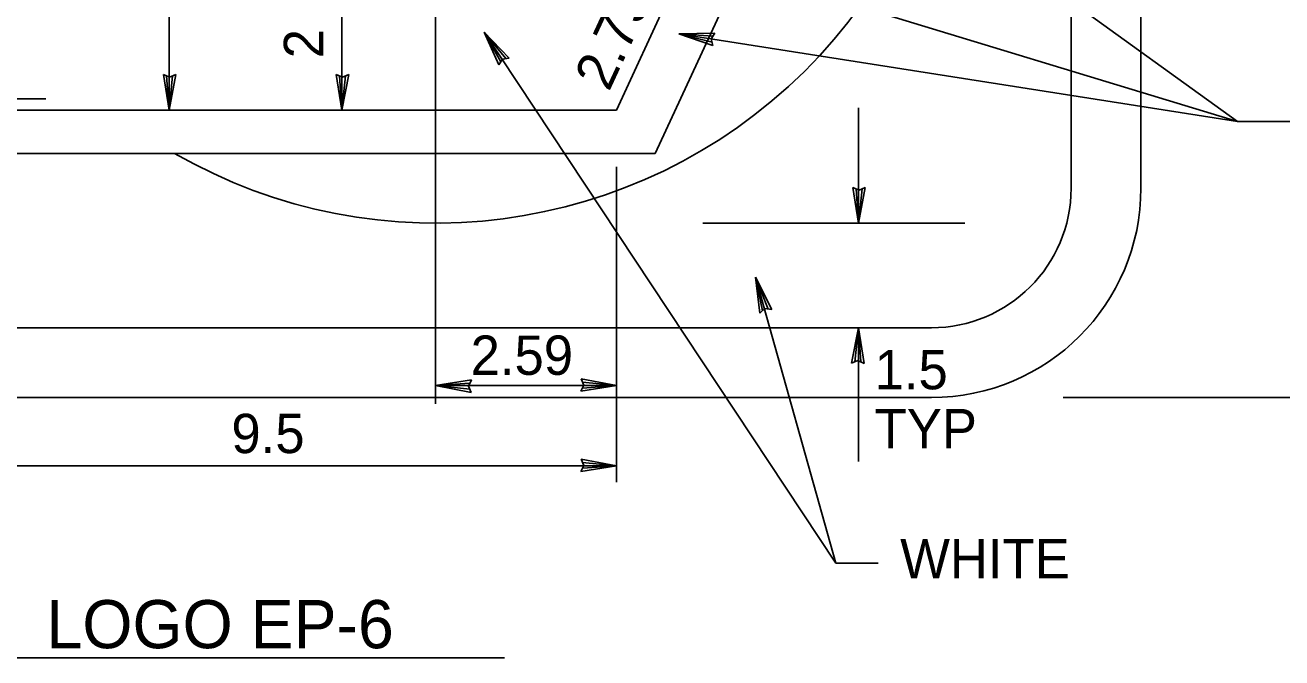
# Model space of a CAD drawing. Extents: x 10268197 to 10269179, y 2141503 to 2142677.
# Drawn here: x 10268537.59 to 10268560.08, y 2141960.82 to 2141972.15 of the extents above; entities that cross this region are included whole.
import ezdxf

# ---------------------------------------------------------------- set-up
doc = ezdxf.new("R2010")
doc.units = 0
for name, color, linetype in [('1', 7, 'Continuous'), ('21', 7, 'Continuous'), ('Default', 7, 'Continuous'), ('TextMisc', 7, 'Continuous'), ('TextShtNo', 7, 'Continuous')]:
    doc.layers.add(name, color=color, linetype=linetype)

msp = doc.modelspace()

# ---------------------------------------------------------------- linework, layer by layer
at = {"layer": '1'}
for p, q in [((10268549.369, 2141977.587), (10268559.29, 2141970.427)), ((10268545.142, 2141974.73), (10268559.29, 2141970.427)), ((10268549.292, 2141971.995), (10268559.29, 2141970.427)), ((10268559.29, 2141970.427), (10268560.422, 2141970.427))]:
    msp.add_line(p, q, dxfattribs=at)
at = {"layer": '21'}
msp.add_line((10268536.456, 2141960.817), (10268546.168, 2141960.817), dxfattribs=at)
at = {"layer": 'Default'}
for p, q in [((10268556.312, 2141969.23), (10268556.312, 2141986.73)), ((10268540.165, 2141970.63), (10268540.165, 2141985.364)), ((10268544.937, 2141965.367), (10268544.937, 2141977.98)), ((10268549.691, 2141973.913), (10268548.175, 2141970.63)), ((10268543.258, 2141970.63), (10268543.258, 2141973.085)), ((10268550.385, 2141973.136), (10268548.869, 2141969.854)), ((10268545.806, 2141972.028), (10268552.098, 2141962.512)), ((10268545.806, 2141972.028), (10268546.255, 2141971.562)), ((10268545.806, 2141972.028), (10268546.07, 2141971.437)), ((10268545.806, 2141972.028), (10268546.105, 2141971.491)), ((10268545.806, 2141972.028), (10268546.193, 2141971.551)), ((10268549.292, 2141971.995), (10268549.937, 2141972.007)), ((10268549.292, 2141971.995), (10268549.901, 2141971.785)), ((10268549.292, 2141971.995), (10268549.886, 2141971.848)), ((10268549.292, 2141971.995), (10268549.902, 2141971.953)), ((10268549.871, 2141971.904), (10268549.937, 2141972.007)), ((10268549.901, 2141971.785), (10268549.871, 2141971.904)), ((10268546.07, 2141971.437), (10268546.136, 2141971.54)), ((10268546.136, 2141971.54), (10268546.255, 2141971.562)), ((10268540.165, 2141970.63), (10268540.064, 2141971.269)), ((10268540.175, 2141971.219), (10268540.064, 2141971.269)), ((10268540.165, 2141970.63), (10268540.122, 2141971.242)), ((10268540.165, 2141970.63), (10268540.288, 2141971.266)), ((10268540.165, 2141970.63), (10268540.229, 2141971.241)), ((10268540.288, 2141971.266), (10268540.175, 2141971.219)), ((10268543.258, 2141970.63), (10268543.157, 2141971.269)), ((10268543.268, 2141971.219), (10268543.157, 2141971.269)), ((10268543.258, 2141970.63), (10268543.215, 2141971.242)), ((10268543.258, 2141970.63), (10268543.381, 2141971.266)), ((10268543.258, 2141970.63), (10268543.322, 2141971.241)), ((10268543.381, 2141971.266), (10268543.268, 2141971.219)), ((10268536.053, 2141970.832), (10268537.961, 2141970.832)), ((10268548.175, 2141970.63), (10268536.927, 2141970.63)), ((10268552.505, 2141968.605), (10268552.505, 2141970.667)), ((10268548.869, 2141969.854), (10268536.569, 2141969.854)), ((10268548.175, 2141963.966), (10268548.175, 2141969.612)), ((10268552.505, 2141968.605), (10268552.404, 2141969.244)), ((10268552.515, 2141969.194), (10268552.404, 2141969.244)), ((10268552.505, 2141968.605), (10268552.462, 2141969.217)), ((10268552.505, 2141968.605), (10268552.628, 2141969.24)), ((10268552.505, 2141968.605), (10268552.569, 2141969.216)), ((10268552.628, 2141969.24), (10268552.515, 2141969.194)), ((10268549.722, 2141968.605), (10268554.409, 2141968.605)), ((10268550.66, 2141967.636), (10268552.098, 2141962.512)), ((10268550.66, 2141967.636), (10268550.952, 2141967.059)), ((10268550.66, 2141967.636), (10268550.738, 2141966.993)), ((10268550.66, 2141967.636), (10268550.787, 2141967.034)), ((10268550.66, 2141967.636), (10268550.889, 2141967.066)), ((10268550.738, 2141966.993), (10268550.831, 2141967.073)), ((10268550.831, 2141967.073), (10268550.952, 2141967.059)), ((10268528.812, 2141966.73), (10268553.812, 2141966.73)), ((10268552.505, 2141966.73), (10268552.382, 2141966.094)), ((10268552.505, 2141966.73), (10268552.441, 2141966.119)), ((10268552.505, 2141964.337), (10268552.505, 2141966.73)), ((10268552.505, 2141966.73), (10268552.606, 2141966.09)), ((10268552.505, 2141966.73), (10268552.548, 2141966.118)), ((10268552.382, 2141966.094), (10268552.495, 2141966.141)), ((10268552.495, 2141966.141), (10268552.606, 2141966.09)), ((10268548.175, 2141965.694), (10268547.54, 2141965.817)), ((10268547.54, 2141965.817), (10268547.587, 2141965.704)), ((10268544.937, 2141965.694), (10268545.576, 2141965.795)), ((10268544.937, 2141965.694), (10268545.549, 2141965.737)), ((10268544.937, 2141965.694), (10268548.175, 2141965.694)), ((10268544.937, 2141965.694), (10268545.573, 2141965.57)), ((10268544.937, 2141965.694), (10268545.548, 2141965.63)), ((10268545.525, 2141965.684), (10268545.576, 2141965.795)), ((10268545.573, 2141965.57), (10268545.525, 2141965.684)), ((10268547.587, 2141965.704), (10268547.536, 2141965.592)), ((10268548.175, 2141965.694), (10268547.536, 2141965.592)), ((10268548.175, 2141965.694), (10268547.563, 2141965.65)), ((10268548.175, 2141965.694), (10268547.564, 2141965.758)), ((10268536.3, 2141964.256), (10268548.175, 2141964.256)), ((10268547.587, 2141964.265), (10268547.536, 2141964.155)), ((10268548.175, 2141964.256), (10268547.536, 2141964.155)), ((10268548.175, 2141964.256), (10268547.54, 2141964.379)), ((10268547.54, 2141964.379), (10268547.587, 2141964.265)), ((10268548.175, 2141964.256), (10268547.563, 2141964.213)), ((10268548.175, 2141964.256), (10268547.564, 2141964.319)), ((10268552.098, 2141962.512), (10268552.855, 2141962.512))]:
    msp.add_line(p, q, dxfattribs=at)
for centre, major_axis, start_param, end_param in [((10268544.936, 2141977.98), (0, 9.375), 2.619545, 5.22594), ((10268553.811, 2141969.23), (0, -2.5), 0, 1.570796)]:
    msp.add_ellipse(centre, major_axis=major_axis, ratio=0.999997, start_param=start_param, end_param=end_param, dxfattribs=at)
at = {"layer": 'TextMisc'}
for p, q in [((10268557.562, 2141969.23), (10268557.562, 2141986.73)), ((10268528.812, 2141965.48), (10268553.812, 2141965.48)), ((10268556.169, 2141965.48), (10268565.745, 2141965.48))]:
    msp.add_line(p, q, dxfattribs=at)
msp.add_ellipse((10268553.811, 2141969.23), major_axis=(0, -3.75), ratio=0.999998, start_param=0, end_param=1.570796, dxfattribs=at)
at = {"layer": 'TextShtNo'}
for p, q in [((10268548.175, 2141970.63), (10268549.333, 2141973.136)), ((10268550.385, 2141973.136), (10268548.869, 2141969.854)), ((10268536.927, 2141970.63), (10268548.175, 2141970.63)), ((10268548.869, 2141969.854), (10268536.569, 2141969.854))]:
    msp.add_line(p, q, dxfattribs=at)

# ---------------------------------------------------------------- texts
at = {"layer": '1'}
for s, height, rotation, p in [('2.75', 0.7047, 65.0602, (10268548.038, 2141970.945)), ('2', 0.705, 90, (10268542.924, 2141971.557))]:
    msp.add_text(s, height=height, rotation=rotation, dxfattribs=at).set_placement(p)
for s, height, p in [('2.59', 0.7047, (10268545.563, 2141965.887)), ('1.5', 0.7047, (10268552.794, 2141965.628)), ('9.5', 0.7047, (10268541.281, 2141964.485)), ('TYP', 0.7047, (10268552.794, 2141964.571)), ('WHITE', 0.7047, (10268553.252, 2141962.24)), ('LOGO EP-6', 0.8624, (10268537.972, 2141960.99))]:
    msp.add_text(s, height=height, dxfattribs=at).set_placement(p)

doc.saveas('drawing.dxf')
